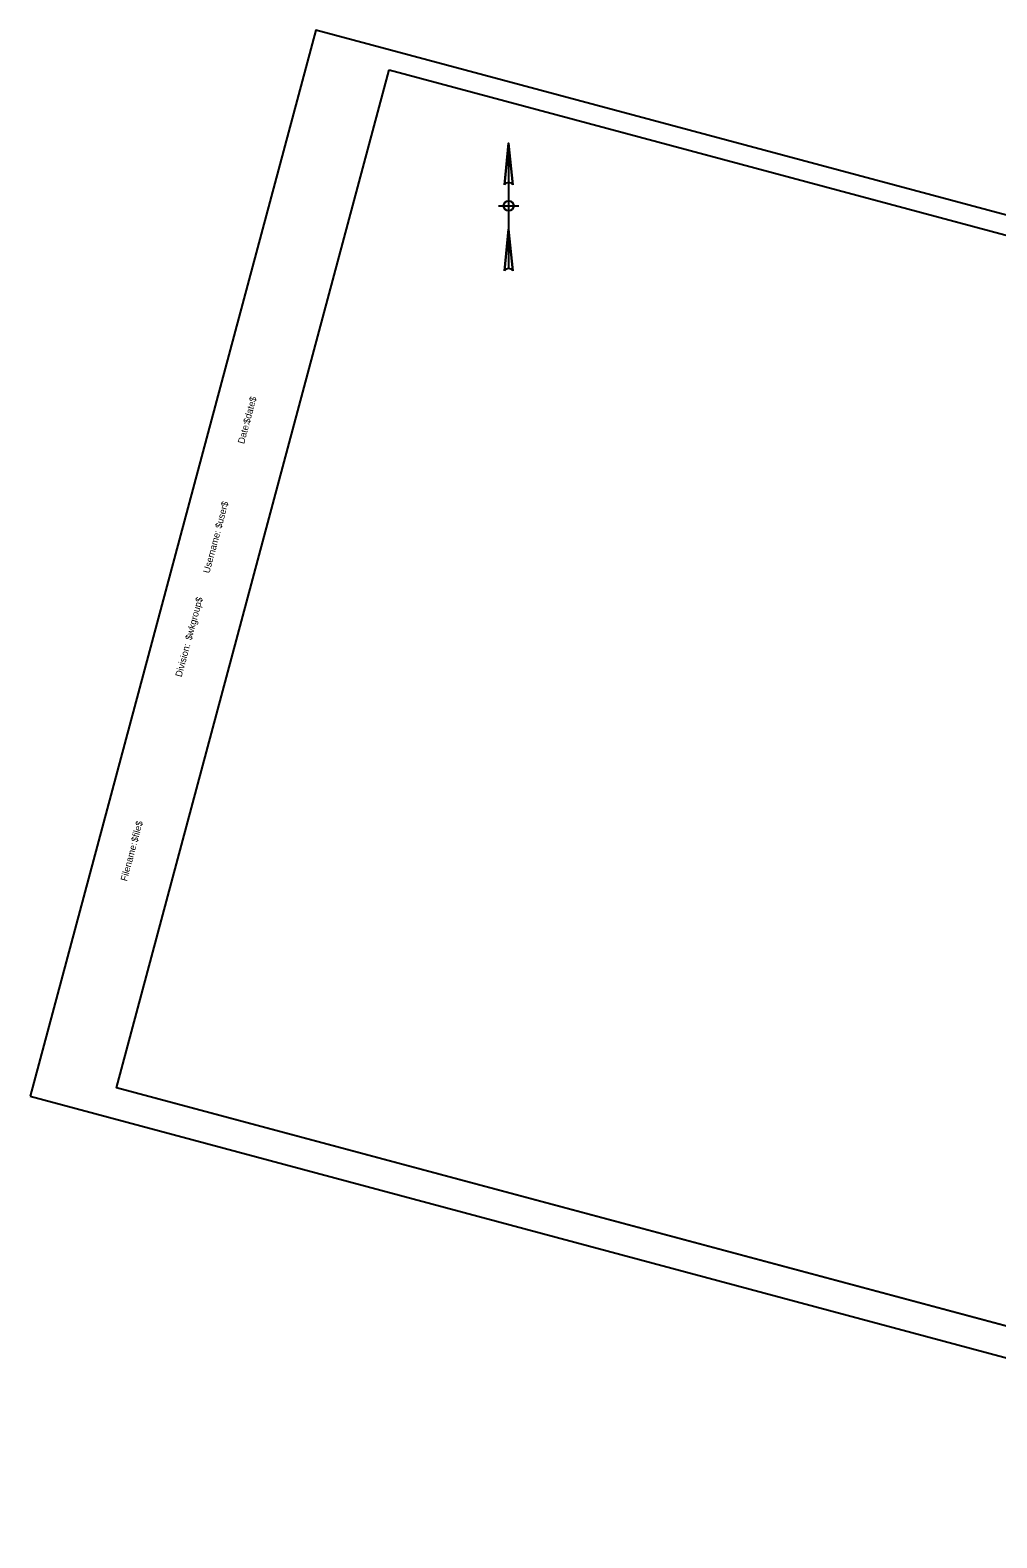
# Model space of a CAD drawing. Extents: x 1763116 to 1764079, y 480561 to 481312.
# Drawn here: x 1763116 to 1763598, y 480561 to 481312 of the extents above; entities that cross this region are included whole.
import ezdxf

# ---------------------------------------------------------------- set-up
doc = ezdxf.new("R2010")
doc.units = 0
for name, color, linetype in [('BORDER', 7, 'Continuous'), ('CLIPS', 7, 'Continuous'), ('H_V CONTROLS', 7, 'Continuous'), ('PLOT BOUNDARY', 7, 'Continuous')]:
    doc.layers.add(name, color=color, linetype=linetype)

msp = doc.modelspace()

# ---------------------------------------------------------------- linework, layer by layer
at = {"layer": 'BORDER'}
msp.add_lwpolyline([(1763294.81, 481292.26), (1764067.55, 481085.21), (1763931.67, 480578.09), (1763158.93, 480785.15)], close=True, dxfattribs=at)
at = {"layer": 'CLIPS'}
msp.add_lwpolyline([(1763294.81, 481292.26), (1764019.26, 481098.15), (1763883.38, 480591.03), (1763158.93, 480785.15)], close=True, dxfattribs=at)
at = {"layer": 'H_V CONTROLS'}
for p, q in [((1763352.23, 481234.97), (1763354.32, 481255.8)), ((1763354.32, 481255.8), (1763354.32, 481193.3)), ((1763354.32, 481255.8), (1763356.4, 481234.97)), ((1763349.32, 481224.55), (1763359.32, 481224.55)), ((1763352.23, 481192.18), (1763354.32, 481213.02)), ((1763354.32, 481213.02), (1763356.4, 481192.18))]:
    msp.add_line(p, q, dxfattribs=at)
for points in [[(1763356.4, 481234.97), (1763354.32, 481255.8), (1763353.27, 481245.39), (1763352.23, 481234.97)], [(1763356.4, 481192.18), (1763354.32, 481213.02), (1763353.27, 481202.6), (1763352.23, 481192.18)]]:
    msp.add_lwpolyline(points, dxfattribs=at)
msp.add_circle((1763354.32, 481224.55), 2.5, dxfattribs=at)
for centre in [(1763354.32, 481233.59), (1763354.32, 481233.59), (1763354.32, 481190.8), (1763354.32, 481190.8)]:
    msp.add_arc(centre, 2.5, 33.55731, 146.44269, dxfattribs=at)
at = {"layer": 'PLOT BOUNDARY'}
msp.add_lwpolyline([(1763115.89, 480780.85), (1763936.92, 480560.85), (1764079.27, 481092.11), (1763258.24, 481312.11)], close=True, dxfattribs=at)

# ---------------------------------------------------------------- texts
at = {"layer": 'BORDER'}
for s, p in [('$date$', (1763225.19, 481115.79)), ('Date:', (1763222.49, 481105.71)), ('$user$', (1763211.2, 481063.57)), ('Username:', (1763205.21, 481041.24)), ('$wkgroup$', (1763196.29, 481007.92)), ('Division:', (1763191.36, 480989.55)), ('$file$', (1763169.31, 480907.25)), ('Filename:', (1763164.1, 480887.8))]:
    msp.add_text(s, height=3.348, rotation=75, dxfattribs=at).set_placement(p)

doc.saveas('drawing.dxf')
